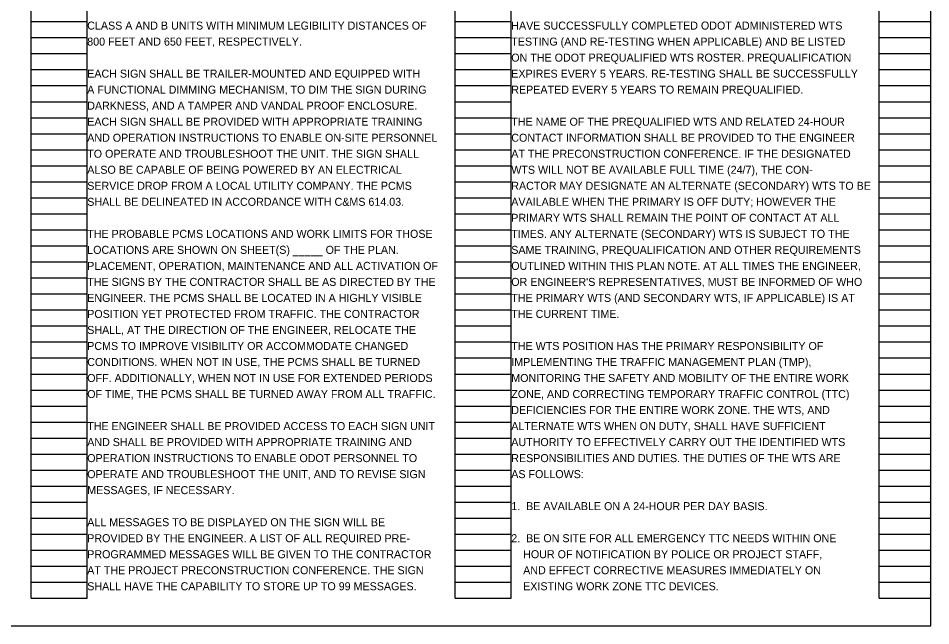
# Model space of a CAD drawing. Extents: x -34 to 2132911, y 0 to 658646.
# Drawn here: x 50.03 to 66, y 0.5 to 11.12 of the extents above; entities that cross this region are included whole.
import ezdxf

# ---------------------------------------------------------------- set-up
doc = ezdxf.new("R2010")
doc.units = 0
for name, color, linetype in [('SC_Scratch1', 7, 'Continuous'), ('SH_Data', 7, 'Continuous'), ('SH_Text', 7, 'Continuous')]:
    doc.layers.add(name, color=color, linetype=linetype)

msp = doc.modelspace()

# ---------------------------------------------------------------- linework, layer by layer
at = {"layer": 'SC_Scratch1'}
msp.add_lwpolyline([(35.5, 0.5), (66, 0.5), (66, 21.5), (35.5, 21.5)], close=True, dxfattribs=at)
at = {"layer": 'SH_Data'}
for p, q in [((50.26, 0.98), (50.26, 21.14)), ((51.24, 0.98), (51.24, 21.14)), ((57.68, 0.98), (57.68, 21.14)), ((58.66, 0.98), (58.66, 21.14)), ((65.1, 0.98), (65.1, 21.14)), ((66, 0.98), (66, 21.14)), ((50.26, 11.06), (51.24, 11.06)), ((57.68, 11.06), (58.66, 11.06)), ((65.1, 11.06), (66, 11.06)), ((50.26, 10.78), (51.24, 10.78)), ((57.68, 10.78), (58.66, 10.78)), ((65.1, 10.78), (66, 10.78)), ((50.26, 10.5), (51.24, 10.5)), ((57.68, 10.5), (58.66, 10.5)), ((65.1, 10.5), (66, 10.5)), ((50.26, 10.22), (51.24, 10.22)), ((57.68, 10.22), (58.66, 10.22)), ((65.1, 10.22), (66, 10.22)), ((50.26, 9.94), (51.24, 9.94)), ((57.68, 9.94), (58.66, 9.94)), ((65.1, 9.94), (66, 9.94)), ((50.26, 9.66), (51.24, 9.66)), ((57.68, 9.66), (58.66, 9.66)), ((65.1, 9.66), (66, 9.66)), ((50.26, 9.38), (51.24, 9.38)), ((57.68, 9.38), (58.66, 9.38)), ((65.1, 9.38), (66, 9.38)), ((50.26, 9.1), (51.24, 9.1)), ((57.68, 9.1), (58.66, 9.1)), ((65.1, 9.1), (66, 9.1)), ((50.26, 8.82), (51.24, 8.82)), ((57.68, 8.82), (58.66, 8.82)), ((65.1, 8.82), (66, 8.82)), ((50.26, 8.54), (51.24, 8.54)), ((57.68, 8.54), (58.66, 8.54)), ((65.1, 8.54), (66, 8.54)), ((50.26, 8.26), (51.24, 8.26)), ((57.68, 8.26), (58.66, 8.26)), ((65.1, 8.26), (66, 8.26)), ((50.26, 7.98), (51.24, 7.98)), ((57.68, 7.98), (58.66, 7.98)), ((65.1, 7.98), (66, 7.98)), ((50.26, 7.7), (51.24, 7.7)), ((57.68, 7.7), (58.66, 7.7)), ((65.1, 7.7), (66, 7.7)), ((50.26, 7.42), (51.24, 7.42)), ((57.68, 7.42), (58.66, 7.42)), ((65.1, 7.42), (66, 7.42)), ((50.26, 7.14), (51.24, 7.14)), ((57.68, 7.14), (58.66, 7.14)), ((65.1, 7.14), (66, 7.14)), ((50.26, 6.86), (51.24, 6.86)), ((57.68, 6.86), (58.66, 6.86)), ((65.1, 6.86), (66, 6.86)), ((50.26, 6.58), (51.24, 6.58)), ((57.68, 6.58), (58.66, 6.58)), ((65.1, 6.58), (66, 6.58)), ((50.26, 6.3), (51.24, 6.3)), ((57.68, 6.3), (58.66, 6.3)), ((65.1, 6.3), (66, 6.3)), ((50.26, 6.02), (51.24, 6.02)), ((57.68, 6.02), (58.66, 6.02)), ((65.1, 6.02), (66, 6.02)), ((50.26, 5.74), (51.24, 5.74)), ((57.68, 5.74), (58.66, 5.74)), ((65.1, 5.74), (66, 5.74)), ((50.26, 5.46), (51.24, 5.46)), ((57.68, 5.46), (58.66, 5.46)), ((65.1, 5.46), (66, 5.46)), ((50.26, 5.18), (51.24, 5.18)), ((57.68, 5.18), (58.66, 5.18)), ((65.1, 5.18), (66, 5.18)), ((50.26, 4.9), (51.24, 4.9)), ((57.68, 4.9), (58.66, 4.9)), ((65.1, 4.9), (66, 4.9)), ((50.26, 4.62), (51.24, 4.62)), ((57.68, 4.62), (58.66, 4.62)), ((65.1, 4.62), (66, 4.62)), ((50.26, 4.34), (51.24, 4.34)), ((57.68, 4.34), (58.66, 4.34)), ((65.1, 4.34), (66, 4.34)), ((50.26, 4.06), (51.24, 4.06)), ((57.68, 4.06), (58.66, 4.06)), ((65.1, 4.06), (66, 4.06)), ((50.26, 3.78), (51.24, 3.78)), ((57.68, 3.78), (58.66, 3.78)), ((65.1, 3.78), (66, 3.78)), ((50.26, 3.5), (51.24, 3.5)), ((57.68, 3.5), (58.66, 3.5)), ((65.1, 3.5), (66, 3.5)), ((50.26, 3.22), (51.24, 3.22)), ((57.68, 3.22), (58.66, 3.22)), ((65.1, 3.22), (66, 3.22)), ((50.26, 2.94), (51.24, 2.94)), ((57.68, 2.94), (58.66, 2.94)), ((65.1, 2.94), (66, 2.94)), ((50.26, 2.66), (51.24, 2.66)), ((57.68, 2.66), (58.66, 2.66)), ((65.1, 2.66), (66, 2.66)), ((50.26, 2.38), (51.24, 2.38)), ((57.68, 2.38), (58.66, 2.38)), ((65.1, 2.38), (66, 2.38)), ((50.26, 2.1), (51.24, 2.1)), ((57.68, 2.1), (58.66, 2.1)), ((65.1, 2.1), (66, 2.1)), ((50.26, 1.82), (51.24, 1.82)), ((57.68, 1.82), (58.66, 1.82)), ((65.1, 1.82), (66, 1.82)), ((50.26, 1.54), (51.24, 1.54)), ((57.68, 1.54), (58.66, 1.54)), ((65.1, 1.54), (66, 1.54)), ((50.26, 1.26), (51.24, 1.26)), ((57.68, 1.26), (58.66, 1.26)), ((65.1, 1.26), (66, 1.26)), ((50.26, 0.98), (51.24, 0.98)), ((57.68, 0.98), (58.66, 0.98)), ((65.1, 0.98), (66, 0.98))]:
    msp.add_line(p, q, dxfattribs=at)

# ---------------------------------------------------------------- texts
at = {"layer": 'SH_Text'}
for s, p in [('CLASS A AND B UNITS WITH MINIMUM LEGIBILITY DISTANCES OF', (51.24, 10.92)), ('HAVE SUCCESSFULLY COMPLETED ODOT ADMINISTERED WTS', (58.66, 10.92)), ('800 FEET AND 650 FEET, RESPECTIVELY.', (51.24, 10.64)), ('TESTING (AND RE-TESTING WHEN APPLICABLE) AND BE LISTED', (58.66, 10.64)), ('ON THE ODOT PREQUALIFIED WTS ROSTER. PREQUALIFICATION', (58.66, 10.36)), ('EACH SIGN SHALL BE TRAILER-MOUNTED AND EQUIPPED WITH', (51.24, 10.08)), ('EXPIRES EVERY 5 YEARS. RE-TESTING SHALL BE SUCCESSFULLY', (58.66, 10.08)), ('A FUNCTIONAL DIMMING MECHANISM, TO DIM THE SIGN DURING', (51.24, 9.8)), ('REPEATED EVERY 5 YEARS TO REMAIN PREQUALIFIED.', (58.66, 9.8)), ('DARKNESS, AND A TAMPER AND VANDAL PROOF ENCLOSURE.', (51.24, 9.52)), ('EACH SIGN SHALL BE PROVIDED WITH APPROPRIATE TRAINING', (51.24, 9.24)), ('THE NAME OF THE PREQUALIFIED WTS AND RELATED 24-HOUR', (58.66, 9.24)), ('AND OPERATION INSTRUCTIONS TO ENABLE ON-SITE PERSONNEL', (51.24, 8.96)), ('CONTACT INFORMATION SHALL BE PROVIDED TO THE ENGINEER', (58.66, 8.96)), ('TO OPERATE AND TROUBLESHOOT THE UNIT. THE SIGN SHALL', (51.24, 8.68)), ('AT THE PRECONSTRUCTION CONFERENCE. IF THE DESIGNATED', (58.66, 8.68)), ('ALSO BE CAPABLE OF BEING POWERED BY AN ELECTRICAL', (51.24, 8.4)), ('WTS WILL NOT BE AVAILABLE FULL TIME (24/7), THE CON-', (58.66, 8.4)), ('SERVICE DROP FROM A LOCAL UTILITY COMPANY. THE PCMS', (51.24, 8.12)), ('RACTOR MAY DESIGNATE AN ALTERNATE (SECONDARY) WTS TO BE', (58.66, 8.12)), ('SHALL BE DELINEATED IN ACCORDANCE WITH C&MS 614.03.', (51.24, 7.84)), ('AVAILABLE WHEN THE PRIMARY IS OFF DUTY; HOWEVER THE', (58.66, 7.84)), ('PRIMARY WTS SHALL REMAIN THE POINT OF CONTACT AT ALL', (58.66, 7.56)), ('THE PROBABLE PCMS LOCATIONS AND WORK LIMITS FOR THOSE', (51.24, 7.28)), ('TIMES. ANY ALTERNATE (SECONDARY) WTS IS SUBJECT TO THE', (58.66, 7.28)), ('LOCATIONS ARE SHOWN ON SHEET(S) _____ OF THE PLAN.', (51.24, 7)), ('SAME TRAINING, PREQUALIFICATION AND OTHER REQUIREMENTS', (58.66, 7)), ('PLACEMENT, OPERATION, MAINTENANCE AND ALL ACTIVATION OF', (51.24, 6.72)), ('OUTLINED WITHIN THIS PLAN NOTE. AT ALL TIMES THE ENGINEER,', (58.66, 6.72)), ('THE SIGNS BY THE CONTRACTOR SHALL BE AS DIRECTED BY THE', (51.24, 6.44)), ("OR ENGINEER'S REPRESENTATIVES, MUST BE INFORMED OF WHO", (58.66, 6.44)), ('ENGINEER. THE PCMS SHALL BE LOCATED IN A HIGHLY VISIBLE', (51.24, 6.16)), ('THE PRIMARY WTS (AND SECONDARY WTS, IF APPLICABLE) IS AT', (58.66, 6.16)), ('POSITION YET PROTECTED FROM TRAFFIC. THE CONTRACTOR', (51.24, 5.88)), ('THE CURRENT TIME.', (58.66, 5.88)), ('SHALL, AT THE DIRECTION OF THE ENGINEER, RELOCATE THE', (51.24, 5.6)), ('PCMS TO IMPROVE VISIBILITY OR ACCOMMODATE CHANGED', (51.24, 5.32)), ('THE WTS POSITION HAS THE PRIMARY RESPONSIBILITY OF', (58.66, 5.32)), ('CONDITIONS. WHEN NOT IN USE, THE PCMS SHALL BE TURNED', (51.24, 5.04)), ('IMPLEMENTING THE TRAFFIC MANAGEMENT PLAN (TMP),', (58.66, 5.04)), ('OFF. ADDITIONALLY, WHEN NOT IN USE FOR EXTENDED PERIODS', (51.24, 4.76)), ('MONITORING THE SAFETY AND MOBILITY OF THE ENTIRE WORK', (58.66, 4.76)), ('OF TIME, THE PCMS SHALL BE TURNED AWAY FROM ALL TRAFFIC.', (51.24, 4.48)), ('ZONE, AND CORRECTING TEMPORARY TRAFFIC CONTROL (TTC)', (58.66, 4.48)), ('DEFICIENCIES FOR THE ENTIRE WORK ZONE. THE WTS, AND', (58.66, 4.2)), ('THE ENGINEER SHALL BE PROVIDED ACCESS TO EACH SIGN UNIT', (51.24, 3.92)), ('ALTERNATE WTS WHEN ON DUTY, SHALL HAVE SUFFICIENT', (58.66, 3.92)), ('AND SHALL BE PROVIDED WITH APPROPRIATE TRAINING AND', (51.24, 3.64)), ('AUTHORITY TO EFFECTIVELY CARRY OUT THE IDENTIFIED WTS', (58.66, 3.64)), ('OPERATION INSTRUCTIONS TO ENABLE ODOT PERSONNEL TO', (51.24, 3.36)), ('RESPONSIBILITIES AND DUTIES. THE DUTIES OF THE WTS ARE', (58.66, 3.36)), ('OPERATE AND TROUBLESHOOT THE UNIT, AND TO REVISE SIGN', (51.24, 3.08)), ('AS FOLLOWS:', (58.66, 3.08)), ('MESSAGES, IF NECESSARY.', (51.24, 2.8)), ('1.  BE AVAILABLE ON A 24-HOUR PER DAY BASIS.', (58.66, 2.52)), ('ALL MESSAGES TO BE DISPLAYED ON THE SIGN WILL BE', (51.24, 2.24)), ('PROVIDED BY THE ENGINEER. A LIST OF ALL REQUIRED PRE-', (51.24, 1.96)), ('2.  BE ON SITE FOR ALL EMERGENCY TTC NEEDS WITHIN ONE', (58.66, 1.96)), ('PROGRAMMED MESSAGES WILL BE GIVEN TO THE CONTRACTOR', (51.24, 1.68)), ('    HOUR OF NOTIFICATION BY POLICE OR PROJECT STAFF,', (58.66, 1.68)), ('AT THE PROJECT PRECONSTRUCTION CONFERENCE. THE SIGN', (51.24, 1.4)), ('    AND EFFECT CORRECTIVE MEASURES IMMEDIATELY ON', (58.66, 1.4)), ('SHALL HAVE THE CAPABILITY TO STORE UP TO 99 MESSAGES.', (51.24, 1.12)), ('    EXISTING WORK ZONE TTC DEVICES.', (58.66, 1.12))]:
    msp.add_text(s, height=0.14, dxfattribs=at).set_placement(p)

doc.saveas('drawing.dxf')
